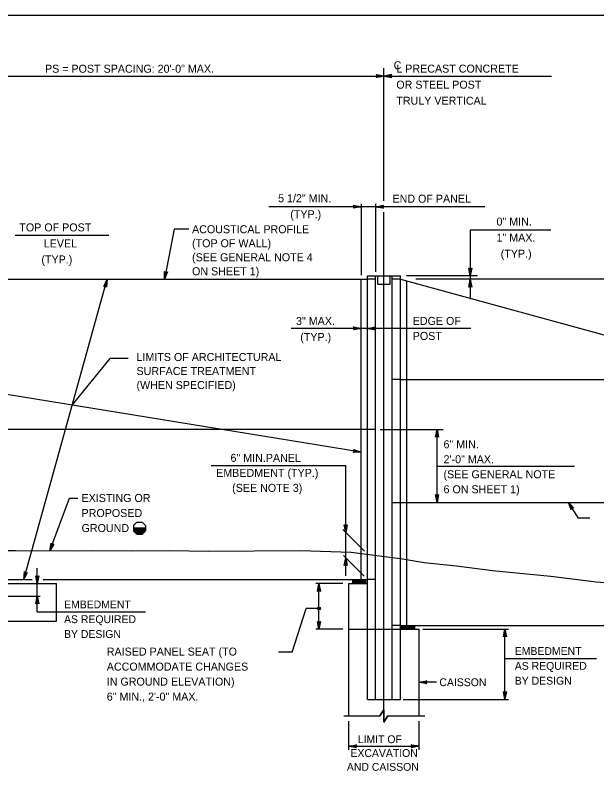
# Model space of a CAD drawing. Extents: x 3761 to 5458, y -616 to 1166.
# Drawn here: x 3937.4 to 4160.9, y 266.7 to 556.7 of the extents above; entities that cross this region are included whole.
import ezdxf

# ---------------------------------------------------------------- set-up
doc = ezdxf.new("R2010")
doc.units = 0
doc.layers.add('1', color=7, linetype='Continuous')
doc.layers.add('2', color=7, linetype='Continuous')

msp = doc.modelspace()

# ---------------------------------------------------------------- linework, layer by layer
at = {"layer": '1'}
for p, q in [((4079.07, 485.44), (4079.07, 536.33)), ((3861.66, 533.3), (4143.42, 533.3)), ((4117.83, 483.16), (4034.88, 483.16)), ((4070.32, 484.22), (4070.32, 456.91)), ((4075.89, 484.22), (4075.89, 458.13)), ((4079.07, 290.13), (4079.07, 481.02)), ((3998.53, 474.51), (3994.8, 455.3)), ((4004.09, 474.51), (3998.53, 474.51)), ((4143.11, 474.16), (4112.25, 474.16)), ((4112.25, 474.16), (4112.25, 447.72)), ((3937.42, 472.24), (3973.37, 472.24)), ((4072.72, 321.06), (4072.72, 456.66)), ((4072.72, 456.66), (4085.41, 456.66)), ((4075.89, 294.08), (4075.89, 456.66)), ((4076.67, 453.46), (4076.67, 456.66)), ((4081.47, 453.46), (4081.47, 456.66)), ((4082.24, 294.08), (4082.24, 456.66)), ((4085.41, 321.06), (4085.41, 456.66)), ((4115.01, 456.66), (4087.75, 456.66)), ((3931.81, 455.3), (4072.72, 455.3)), ((3940.74, 340.1), (3972.8, 455.3)), ((4070.32, 340.1), (4070.32, 455.3)), ((4075.89, 455.3), (4072.72, 455.3)), ((4076.67, 453.46), (4081.47, 453.46)), ((4085.41, 455.3), (4082.24, 455.3)), ((4085.41, 455.3), (4226.32, 416.9)), ((4087.81, 322.48), (4087.81, 454.65)), ((4170.46, 455.3), (4091.37, 455.3)), ((4112.39, 436.47), (4043.47, 436.47)), ((3959.35, 406.96), (3973.87, 424.97)), ((3980.78, 424.97), (3973.87, 424.97)), ((4085.41, 416.9), (4082.24, 416.9)), ((4085.41, 416.9), (4226.32, 416.9)), ((4070.32, 388.95), (3934.21, 411.04)), ((4075.89, 397.7), (3928.64, 397.7)), ((4077.65, 397.7), (4101.82, 397.7)), ((4099.45, 369.69), (4099.45, 397.7)), ((4012.77, 383.87), (4064.4, 383.87)), ((4064.4, 341.49), (4064.4, 383.87)), ((4099.45, 383.57), (4152.2, 383.57)), ((3950.76, 351.12), (3958.27, 371.3)), ((3958.27, 371.3), (3961.54, 371.3)), ((4082.24, 369.69), (4229.66, 369.69)), ((4153.8, 363.58), (4149.89, 369.69)), ((4158.2, 363.58), (4153.8, 363.58)), ((3982.89, 359.91), (3987.51, 359.91)), ((3984.15, 362.1), (3982.9, 360.85)), ((3982.9, 360.85), (3982.9, 358.73)), ((3982.91, 359.81), (3987.51, 359.81)), ((3982.91, 359.71), (3987.51, 359.71)), ((3984.15, 362.1), (3986.27, 362.1)), ((3986, 359.91), (3987.51, 359.91)), ((3986.27, 362.1), (3987.52, 360.85)), ((3987.52, 360.85), (3987.52, 358.73)), ((3982.89, 358.81), (3987.51, 358.81)), ((3982.9, 359.31), (3987.51, 359.31)), ((3982.9, 359.21), (3987.51, 359.21)), ((3982.9, 359.11), (3987.51, 359.11)), ((3982.9, 359.01), (3987.51, 359.01)), ((3982.9, 358.91), (3987.51, 358.91)), ((3984.15, 357.48), (3982.9, 358.73)), ((3982.91, 359.61), (3987.51, 359.61)), ((3982.91, 359.51), (3987.51, 359.51)), ((3982.91, 359.41), (3987.51, 359.41)), ((3982.91, 358.71), (3987.47, 358.71)), ((3983.01, 358.61), (3987.37, 358.61)), ((3983.12, 358.51), (3987.27, 358.51)), ((3983.22, 358.41), (3987.18, 358.41)), ((3983.32, 358.31), (3987.08, 358.31)), ((3983.42, 358.21), (3986.99, 358.21)), ((3983.52, 358.11), (3986.89, 358.11)), ((3983.63, 358.01), (3986.79, 358.01)), ((3983.73, 357.91), (3986.7, 357.91)), ((3983.83, 357.81), (3986.6, 357.81)), ((3983.93, 357.71), (3986.51, 357.71)), ((3984.03, 357.61), (3986.41, 357.61)), ((3984.13, 357.51), (3986.31, 357.51)), ((3984.15, 357.48), (3986.27, 357.48)), ((3986.27, 357.48), (3987.52, 358.73)), ((4063.25, 359.3), (4071.6, 350.95)), ((4063.54, 349.28), (4071.5, 341.32)), ((3945.93, 327.65), (3945.93, 344.4)), ((3931.81, 340.1), (3944.01, 340.1)), ((3948.18, 340.1), (4072.63, 340.1)), ((4067.16, 338.52), (4067.16, 340.1)), ((4067.16, 339.92), (4072.16, 339.92)), ((4067.16, 339.72), (4072.16, 339.72)), ((4067.16, 339.52), (4072.16, 339.52)), ((4072.16, 338.52), (4072.16, 340.1)), ((4075.81, 340.1), (4072.63, 340.1)), ((3897.57, 338.52), (3953.36, 338.52)), ((3953.36, 324.12), (3953.36, 338.52)), ((4063.32, 338.52), (4052.96, 338.52)), ((4054.11, 321.06), (4054.11, 338.52)), ((4065.57, 287.73), (4065.57, 338.52)), ((4065.57, 338.52), (4072.72, 338.52)), ((4067.16, 339.32), (4072.16, 339.32)), ((4067.16, 339.12), (4072.16, 339.12)), ((4067.16, 338.92), (4072.16, 338.92)), ((4067.16, 338.72), (4072.16, 338.72)), ((3932.96, 333.72), (3947.1, 333.72)), ((4043.78, 312.25), (4049.2, 328.96)), ((4054.11, 328.96), (4049.2, 328.96)), ((3945.93, 327.65), (3987.55, 327.65)), ((3897.57, 324.12), (3953.36, 324.12)), ((4085.41, 322.48), (4082.24, 322.48)), ((4085.41, 322.48), (4226.4, 322.48)), ((4085.97, 321.06), (4085.97, 322.48)), ((4085.97, 322.26), (4090.97, 322.26)), ((4085.97, 322.06), (4090.97, 322.06)), ((4090.97, 321.06), (4090.97, 322.48)), ((4063.32, 321.06), (4052.96, 321.06)), ((4065.57, 321.06), (4092.56, 321.06)), ((4072.72, 294.08), (4072.72, 321.06)), ((4085.41, 294.08), (4085.41, 321.06)), ((4085.97, 321.86), (4090.97, 321.86)), ((4085.97, 321.66), (4090.97, 321.66)), ((4085.97, 321.46), (4090.97, 321.46)), ((4085.97, 321.26), (4090.97, 321.26)), ((4092.56, 287.73), (4092.56, 321.06)), ((4094.03, 321.06), (4126.88, 321.06)), ((4125.55, 294.08), (4125.55, 321.06)), ((4043.78, 312.25), (4038.56, 312.25)), ((4125.55, 309.75), (4160.65, 309.75)), ((4099.22, 300.67), (4092.56, 300.67)), ((4072.72, 294.08), (4085.41, 294.08)), ((4086.5, 294.08), (4126.88, 294.08)), ((4077.51, 287.73), (4079.03, 290.08)), ((4079.03, 290.08), (4079.01, 285.38)), ((4063.72, 287.73), (4077.51, 287.73)), ((4079.01, 285.38), (4080.53, 287.73)), ((4080.53, 287.73), (4094.75, 287.73)), ((4065.57, 274.75), (4065.57, 285.8)), ((4092.56, 274.75), (4092.56, 285.8)), ((4065.57, 276.11), (4092.56, 276.11))]:
    msp.add_line(p, q, dxfattribs=at)
for points in [[(4079.07, 533.3), (4076.08, 532.74), (4076.2, 532.82), (4076.31, 532.9), (4076.37, 533), (4076.43, 533.1), (4076.45, 533.2), (4076.47, 533.3), (4076.45, 533.4), (4076.43, 533.5), (4076.37, 533.6), (4076.31, 533.7), (4076.2, 533.78), (4076.08, 533.86), (4079.07, 533.3), (4076.2, 533.78), (4076.31, 533.7), (4079.07, 533.3), (4076.37, 533.6), (4076.43, 533.5), (4079.07, 533.3), (4076.45, 533.4), (4076.47, 533.3), (4079.07, 533.3), (4076.45, 533.2), (4076.43, 533.1), (4079.07, 533.3), (4076.37, 533), (4076.31, 532.9), (4079.07, 533.3), (4076.2, 532.82)], [(4079.07, 533.3), (4082.05, 532.74), (4081.93, 532.82), (4081.82, 532.9), (4081.76, 533), (4081.7, 533.1), (4081.68, 533.2), (4081.67, 533.3), (4081.68, 533.4), (4081.7, 533.5), (4081.76, 533.6), (4081.82, 533.7), (4081.93, 533.78), (4082.05, 533.86), (4079.07, 533.3), (4081.93, 533.78), (4081.82, 533.7), (4079.07, 533.3), (4081.76, 533.6), (4081.7, 533.5), (4079.07, 533.3), (4081.68, 533.4), (4081.67, 533.3), (4079.07, 533.3), (4081.68, 533.2), (4081.7, 533.1), (4079.07, 533.3), (4081.76, 533), (4081.82, 532.9), (4079.07, 533.3), (4081.93, 532.82)], [(4070.32, 483.16), (4067.33, 482.6), (4067.56, 482.76), (4067.68, 482.96), (4067.72, 483.16), (4067.68, 483.36), (4067.56, 483.56), (4067.33, 483.72), (4070.32, 483.16), (4067.56, 483.56), (4067.68, 483.36), (4070.32, 483.16), (4067.72, 483.16), (4067.68, 482.96), (4070.32, 483.16), (4067.56, 482.76)], [(4075.89, 483.16), (4078.87, 483.72), (4078.64, 483.56), (4078.52, 483.36), (4078.49, 483.16), (4078.52, 482.96), (4078.64, 482.76), (4078.87, 482.6), (4075.89, 483.16), (4078.64, 482.76), (4078.52, 482.96), (4075.89, 483.16), (4078.49, 483.16), (4078.52, 483.36), (4075.89, 483.16), (4078.64, 483.56)], [(3994.8, 455.3), (3994.82, 458.34), (3994.88, 458.21), (3994.93, 458.08), (3995.02, 458), (3995.11, 457.93), (3995.2, 457.89), (3995.3, 457.86), (3995.4, 457.85), (3995.5, 457.85), (3995.61, 457.89), (3995.72, 457.93), (3995.82, 458.03), (3995.92, 458.12), (3994.8, 455.3), (3995.82, 458.03), (3995.72, 457.93), (3994.8, 455.3), (3995.61, 457.89), (3995.5, 457.85), (3994.8, 455.3), (3995.4, 457.85), (3995.3, 457.86), (3994.8, 455.3), (3995.2, 457.89), (3995.11, 457.93), (3994.8, 455.3), (3995.02, 458), (3994.93, 458.08), (3994.8, 455.3), (3994.88, 458.21)], [(4112.25, 456.66), (4111.69, 459.64), (4111.77, 459.52), (4111.85, 459.41), (4111.95, 459.35), (4112.05, 459.29), (4112.15, 459.27), (4112.25, 459.26), (4112.35, 459.27), (4112.45, 459.29), (4112.55, 459.35), (4112.65, 459.41), (4112.73, 459.52), (4112.81, 459.64), (4112.25, 456.66), (4112.73, 459.52), (4112.65, 459.41), (4112.25, 456.66), (4112.55, 459.35), (4112.45, 459.29), (4112.25, 456.66), (4112.35, 459.27), (4112.25, 459.26), (4112.25, 456.66), (4112.15, 459.27), (4112.05, 459.29), (4112.25, 456.66), (4111.95, 459.35), (4111.85, 459.41), (4112.25, 456.66), (4111.77, 459.52)], [(3972.8, 455.3), (3972.54, 452.28), (3972.45, 452.54), (3972.29, 452.71), (3972.1, 452.8), (3971.9, 452.82), (3971.68, 452.76), (3971.46, 452.58), (3972.8, 455.3), (3971.68, 452.76), (3971.9, 452.82), (3972.8, 455.3), (3972.1, 452.8), (3972.29, 452.71), (3972.8, 455.3), (3972.45, 452.54)], [(4112.25, 455.3), (4112.81, 452.32), (4112.73, 452.44), (4112.65, 452.55), (4112.55, 452.61), (4112.45, 452.67), (4112.35, 452.69), (4112.25, 452.7), (4112.15, 452.69), (4112.05, 452.67), (4111.95, 452.61), (4111.85, 452.55), (4111.77, 452.44), (4111.69, 452.32), (4112.25, 455.3), (4111.77, 452.44), (4111.85, 452.55), (4112.25, 455.3), (4111.95, 452.61), (4112.05, 452.67), (4112.25, 455.3), (4112.15, 452.69), (4112.25, 452.7), (4112.25, 455.3), (4112.35, 452.69), (4112.45, 452.67), (4112.25, 455.3), (4112.55, 452.61), (4112.65, 452.55), (4112.25, 455.3), (4112.73, 452.44)], [(4070.32, 436.47), (4067.33, 435.92), (4067.56, 436.07), (4067.68, 436.27), (4067.72, 436.47), (4067.68, 436.67), (4067.56, 436.87), (4067.33, 437.03), (4070.32, 436.47), (4067.56, 436.87), (4067.68, 436.67), (4070.32, 436.47), (4067.72, 436.47), (4067.68, 436.27), (4070.32, 436.47), (4067.56, 436.07)], [(4072.72, 436.47), (4075.7, 437.03), (4075.47, 436.87), (4075.35, 436.67), (4075.32, 436.47), (4075.35, 436.27), (4075.47, 436.07), (4075.7, 435.92), (4072.72, 436.47), (4075.47, 436.07), (4075.35, 436.27), (4072.72, 436.47), (4075.32, 436.47), (4075.35, 436.67), (4072.72, 436.47), (4075.47, 436.87)], [(4099.45, 397.7), (4100.01, 394.72), (4099.85, 394.95), (4099.65, 395.07), (4099.45, 395.1), (4099.25, 395.07), (4099.05, 394.95), (4098.89, 394.72), (4099.45, 397.7), (4099.05, 394.95), (4099.25, 395.07), (4099.45, 397.7), (4099.45, 395.1), (4099.65, 395.07), (4099.45, 397.7), (4099.85, 394.95)], [(4070.32, 388.95), (4067.28, 388.87), (4067.53, 388.99), (4067.68, 389.17), (4067.75, 389.36), (4067.75, 389.57), (4067.66, 389.78), (4067.46, 389.98), (4070.32, 388.95), (4067.66, 389.78), (4067.75, 389.57), (4070.32, 388.95), (4067.75, 389.36), (4067.68, 389.17), (4070.32, 388.95), (4067.53, 388.99)], [(4099.45, 369.69), (4098.89, 372.67), (4099.05, 372.44), (4099.25, 372.32), (4099.45, 372.29), (4099.65, 372.32), (4099.85, 372.44), (4100.01, 372.67), (4099.45, 369.69), (4099.85, 372.44), (4099.65, 372.32), (4099.45, 369.69), (4099.45, 372.29), (4099.25, 372.32), (4099.45, 369.69), (4099.05, 372.44)], [(4149.89, 369.69), (4151.97, 367.48), (4151.71, 367.59), (4151.48, 367.58), (4151.29, 367.5), (4151.14, 367.36), (4151.04, 367.16), (4151.03, 366.88), (4149.89, 369.69), (4151.04, 367.16), (4151.14, 367.36), (4149.89, 369.69), (4151.29, 367.5), (4151.48, 367.58), (4149.89, 369.69), (4151.71, 367.59)], [(4064.4, 358.15), (4063.84, 361.14), (4063.92, 361.02), (4064, 360.91), (4064.1, 360.85), (4064.2, 360.79), (4064.3, 360.77), (4064.4, 360.75), (4064.5, 360.77), (4064.6, 360.79), (4064.7, 360.85), (4064.8, 360.91), (4064.88, 361.02), (4064.96, 361.14), (4064.4, 358.15), (4064.88, 361.02), (4064.8, 360.91), (4064.4, 358.15), (4064.7, 360.85), (4064.6, 360.79), (4064.4, 358.15), (4064.5, 360.77), (4064.4, 360.75), (4064.4, 358.15), (4064.3, 360.77), (4064.2, 360.79), (4064.4, 358.15), (4064.1, 360.85), (4064, 360.91), (4064.4, 358.15), (4063.92, 361.02)], [(3950.76, 351.12), (3951.28, 354.11), (3951.31, 353.97), (3951.35, 353.84), (3951.42, 353.74), (3951.49, 353.65), (3951.58, 353.6), (3951.67, 353.55), (3951.77, 353.53), (3951.87, 353.51), (3951.98, 353.54), (3952.1, 353.56), (3952.21, 353.64), (3952.33, 353.72), (3950.76, 351.12), (3952.21, 353.64), (3952.1, 353.56), (3950.76, 351.12), (3951.98, 353.54), (3951.87, 353.51), (3950.76, 351.12), (3951.77, 353.53), (3951.67, 353.55), (3950.76, 351.12), (3951.58, 353.6), (3951.49, 353.65), (3950.76, 351.12), (3951.42, 353.74), (3951.35, 353.84), (3950.76, 351.12), (3951.31, 353.97)], [(3861.98, 350.45), (3878.35, 350.9), (3891.12, 350.32), (3914.31, 351.17), (3937.57, 351.17), (3961.32, 351.07), (3966.64, 351.17), (3982.01, 351.07), (3996.76, 351.17), (4011.56, 350.95), (4046.92, 351.17), (4066.47, 350.64), (4086.26, 348.09), (4094.49, 346.67), (4106.93, 345.35), (4120.71, 343.61), (4143.22, 341.33), (4160.6, 339.19), (4243, 332.75), (4279.86, 332.38)], [(4064.4, 348.43), (4064.96, 345.44), (4064.88, 345.56), (4064.8, 345.67), (4064.7, 345.73), (4064.6, 345.79), (4064.5, 345.81), (4064.4, 345.83), (4064.3, 345.81), (4064.2, 345.79), (4064.1, 345.73), (4064, 345.67), (4063.92, 345.56), (4063.84, 345.44), (4064.4, 348.43), (4063.92, 345.56), (4064, 345.67), (4064.4, 348.43), (4064.1, 345.73), (4064.2, 345.79), (4064.4, 348.43), (4064.3, 345.81), (4064.4, 345.83), (4064.4, 348.43), (4064.5, 345.81), (4064.6, 345.79), (4064.4, 348.43), (4064.7, 345.73), (4064.8, 345.67), (4064.4, 348.43), (4064.88, 345.56)], [(3940.74, 340.1), (3941, 343.13), (3941.09, 342.86), (3941.25, 342.7), (3941.43, 342.61), (3941.64, 342.59), (3941.86, 342.65), (3942.08, 342.83), (3940.74, 340.1), (3941.86, 342.65), (3941.64, 342.59), (3940.74, 340.1), (3941.43, 342.61), (3941.25, 342.7), (3940.74, 340.1), (3941.09, 342.86)], [(3945.93, 338.52), (3945.37, 341.5), (3945.45, 341.38), (3945.53, 341.27), (3945.63, 341.21), (3945.73, 341.15), (3945.83, 341.13), (3945.93, 341.12), (3946.03, 341.13), (3946.13, 341.15), (3946.23, 341.21), (3946.33, 341.27), (3946.41, 341.38), (3946.49, 341.5), (3945.93, 338.52), (3946.41, 341.38), (3946.33, 341.27), (3945.93, 338.52), (3946.23, 341.21), (3946.13, 341.15), (3945.93, 338.52), (3946.03, 341.13), (3945.93, 341.12), (3945.93, 338.52), (3945.83, 341.13), (3945.73, 341.15), (3945.93, 338.52), (3945.63, 341.21), (3945.53, 341.27), (3945.93, 338.52), (3945.45, 341.38)], [(4054.11, 338.52), (4054.67, 335.53), (4054.59, 335.65), (4054.51, 335.76), (4054.41, 335.82), (4054.31, 335.88), (4054.21, 335.9), (4054.11, 335.92), (4054.01, 335.9), (4053.91, 335.88), (4053.81, 335.82), (4053.71, 335.76), (4053.63, 335.65), (4053.55, 335.53), (4054.11, 338.52), (4053.63, 335.65), (4053.71, 335.76), (4054.11, 338.52), (4053.81, 335.82), (4053.91, 335.88), (4054.11, 338.52), (4054.01, 335.9), (4054.11, 335.92), (4054.11, 338.52), (4054.21, 335.9), (4054.31, 335.88), (4054.11, 338.52), (4054.41, 335.82), (4054.51, 335.76), (4054.11, 338.52), (4054.59, 335.65)], [(3945.93, 333.72), (3946.49, 330.73), (3946.41, 330.85), (3946.33, 330.96), (3946.23, 331.02), (3946.13, 331.08), (3946.03, 331.1), (3945.93, 331.12), (3945.83, 331.1), (3945.73, 331.08), (3945.63, 331.02), (3945.53, 330.96), (3945.45, 330.85), (3945.37, 330.73), (3945.93, 333.72), (3945.45, 330.85), (3945.53, 330.96), (3945.93, 333.72), (3945.63, 331.02), (3945.73, 331.08), (3945.93, 333.72), (3945.83, 331.1), (3945.93, 331.12), (3945.93, 333.72), (3946.03, 331.1), (3946.13, 331.08), (3945.93, 333.72), (3946.23, 331.02), (3946.33, 330.96), (3945.93, 333.72), (3946.41, 330.85)], [(4054.11, 321.06), (4053.55, 324.04), (4053.63, 323.92), (4053.71, 323.81), (4053.81, 323.75), (4053.91, 323.69), (4054.01, 323.67), (4054.11, 323.66), (4054.21, 323.67), (4054.31, 323.69), (4054.41, 323.75), (4054.51, 323.81), (4054.59, 323.92), (4054.67, 324.04), (4054.11, 321.06), (4054.59, 323.92), (4054.51, 323.81), (4054.11, 321.06), (4054.41, 323.75), (4054.31, 323.69), (4054.11, 321.06), (4054.21, 323.67), (4054.11, 323.66), (4054.11, 321.06), (4054.01, 323.67), (4053.91, 323.69), (4054.11, 321.06), (4053.81, 323.75), (4053.71, 323.81), (4054.11, 321.06), (4053.63, 323.92)], [(4125.55, 321.06), (4126.11, 318.07), (4125.95, 318.3), (4125.75, 318.42), (4125.55, 318.46), (4125.35, 318.42), (4125.15, 318.3), (4124.99, 318.07), (4125.55, 321.06), (4125.15, 318.3), (4125.35, 318.42), (4125.55, 321.06), (4125.55, 318.46), (4125.75, 318.42), (4125.55, 321.06), (4125.95, 318.3)], [(4092.56, 300.67), (4095.54, 301.23), (4095.31, 301.07), (4095.19, 300.87), (4095.16, 300.67), (4095.19, 300.47), (4095.31, 300.27), (4095.54, 300.11), (4092.56, 300.67), (4095.31, 300.27), (4095.19, 300.47), (4092.56, 300.67), (4095.16, 300.67), (4095.19, 300.87), (4092.56, 300.67), (4095.31, 301.07)], [(4125.55, 294.08), (4124.99, 297.06), (4125.15, 296.83), (4125.35, 296.71), (4125.55, 296.68), (4125.75, 296.71), (4125.95, 296.83), (4126.11, 297.06), (4125.55, 294.08), (4125.95, 296.83), (4125.75, 296.71), (4125.55, 294.08), (4125.55, 296.68), (4125.35, 296.71), (4125.55, 294.08), (4125.15, 296.83)], [(4063.72, 287.73), (4077.51, 287.73), (4079.03, 290.08), (4079.01, 285.38), (4080.53, 287.73), (4094.75, 287.73)], [(4080.53, 287.73), (4079.01, 285.38), (4079.03, 290.08), (4077.51, 287.73)], [(4065.57, 276.11), (4068.55, 276.66), (4068.32, 276.51), (4068.21, 276.31), (4068.17, 276.11), (4068.21, 275.91), (4068.32, 275.71), (4068.55, 275.55), (4065.57, 276.11), (4068.32, 275.71), (4068.21, 275.91), (4065.57, 276.11), (4068.17, 276.11), (4068.21, 276.31), (4065.57, 276.11), (4068.32, 276.51)], [(4092.56, 276.11), (4089.57, 275.55), (4089.8, 275.71), (4089.92, 275.91), (4089.96, 276.11), (4089.92, 276.31), (4089.8, 276.51), (4089.57, 276.66), (4092.56, 276.11), (4089.8, 276.51), (4089.92, 276.31), (4092.56, 276.11), (4089.96, 276.11), (4089.92, 275.91), (4092.56, 276.11), (4089.8, 275.71)]]:
    msp.add_lwpolyline(points, dxfattribs=at)
for radius in [0.533, 0.267]:
    msp.add_circle((4054.11, 328.96), radius, dxfattribs=at)
at = {"layer": '2'}
msp.add_line((3801.34, 556.69), (4587.34, 556.69), dxfattribs=at)

# ---------------------------------------------------------------- texts
at = {"layer": '1'}
for s, height, p in [('PS = POST SPACING: 20\'-0" MAX.', 3.072, (3948.9, 534.58)), ('C', 3.07, (4082.81, 535.9)), ('L PRECAST CONCRETE ', 3.072, (4083.83, 534.62)), ('OR STEEL POST', 3.072, (4083.83, 528.47)), ('TRULY VERTICAL', 3.072, (4083.83, 522.33)), ('5 1/2" MIN.', 3.072, (4038.42, 484.89)), ('END OF PANEL', 3.072, (4082.36, 484.71)), ('(TYP.)', 3.072, (4043.1, 478.74)), ('0" MIN.', 3.072, (4122.31, 475.91)), ('TOP OF POST', 3.072, (3939.06, 473.69)), ('ACOUSTICAL PROFILE', 3.072, (4005.38, 472.98)), ('1" MAX.', 3.072, (4122.31, 469.76)), ('LEVEL', 3.072, (3948.42, 467.55)), ('(TOP OF WALL)', 3.072, (4005.38, 467.61)), ('(TYP.)', 3.072, (3947.52, 461.4)), ('(SEE GENERAL NOTE 4', 3.072, (4005.38, 462.23)), ('(TYP.)', 3.072, (4123.92, 463.62)), ('ON SHEET 1)', 3.072, (4005.38, 456.86)), ('3" MAX.', 3.072, (4045.32, 437.77)), ('EDGE OF', 3.072, (4090.13, 437.8)), ('POST', 3.072, (4090.13, 432.04)), ('(TYP.)', 3.072, (4046.93, 431.63)), ('LIMITS OF ARCHITECTURAL', 3.072, (3984.04, 423.95)), ('SURFACE TREATMENT', 3.072, (3984.04, 418.57)), ('(WHEN SPECIFIED)', 3.072, (3984.04, 413.2)), ('6" MIN.', 3.072, (4101.96, 390.47)), ('6" MIN.PANEL', 3.072, (4020.15, 385.25)), ('2\'-0" MAX.', 3.072, (4101.96, 384.71)), ('EMBEDMENT (TYP.)', 3.072, (4014.64, 379.49)), ('(SEE GENERAL NOTE', 3.072, (4101.96, 378.95)), ('(SEE NOTE 3)', 3.072, (4020.78, 373.73)), ('6 ON SHEET 1)', 3.072, (4101.96, 373.19)), ('EXISTING OR ', 3.072, (3962.94, 369.84)), ('PROPOSED', 3.072, (3962.94, 364.08)), ('GROUND', 3.072, (3962.94, 358.32)), ('EMBEDMENT', 3, (3956.22, 329.04)), ('AS REQUIRED', 3, (3956.22, 323.36)), ('BY DESIGN', 3, (3956.22, 317.67)), ('RAISED PANEL SEAT (TO', 3.072, (3972.63, 310.9)), ('EMBEDMENT', 3, (4129.33, 311.14)), ('ACCOMMODATE CHANGES', 3.072, (3972.63, 305.14)), ('AS REQUIRED', 3, (4129.33, 305.45)), ('IN GROUND ELEVATION)', 3.072, (3972.63, 299.38)), ('CAISSON', 3, (4100.37, 299.17)), ('BY DESIGN', 3, (4129.33, 299.76)), ('6" MIN., 2\'-0" MAX.', 3.072, (3972.63, 293.62)), ('LIMIT OF', 3, (4069.02, 277.31)), ('EXCAVATION', 3, (4066.21, 272)), ('AND CAISSON', 3, (4064.83, 266.7))]:
    msp.add_text(s, height=height, dxfattribs=at).set_placement(p)

doc.saveas('drawing.dxf')
